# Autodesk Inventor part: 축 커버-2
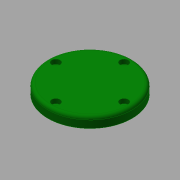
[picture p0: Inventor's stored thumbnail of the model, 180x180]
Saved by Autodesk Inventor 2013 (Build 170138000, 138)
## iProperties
Created: 2015-10
Part Number: 축 커버-2
Document SubType Name: Modeling
Designer: mdu
Density: 7.86 g/cm^3
Material: 강철, 연강
Mass: 403.237 g
Surface Area: 134.748 cm^2
Volume: 51.3024 cm^3
Author: mdu
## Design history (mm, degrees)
sketch "스케치1"
  geometry: C1 r 40 at (0, 0) reference; C2 r 26 at (0, 0) reference; 1 further point
  node "참조1"
  node "참조2"
extrude "돌출1" new body sketch "스케치1" distance "d0" = 10; taper "d1" = 0 deg
extrude "돌출2" join sketch "스케치1" distance "d2" = 3; taper "d3" = 0 deg
sketch "스케치2"
  geometry: C1 r 20 at (0, 0); 1 further point
  constraints: 1 centre point, 1 coincident
  dimensions: "d13" = 40 diameter of C1
extrude "돌출3" cut sketch "스케치2" distance "d14" = 3; taper "d15" = 0 deg
sketch "스케치3"
  geometry: C1 r 1.621 at (0, 32.5) reference; 1 further point
hole "구멍2" sketch "스케치3" at (0, 32.5) diameter "d16" = 4.5; stored, may be unused: countersink angle "d20" = 90 deg, drill point angle "d22" = 118 deg; dims "d17" = 6, "d18" = 8, "d19" = 4.4, "d21" = 8
fillet "모깎기1" dims "d26" = 3, "d27" = 0.3
chamfer "모따기1" distance "d28" = 1; stored, may be unused: second distance "d29" = 2, angle "d30" = 45 deg
node "솔리드1"
pattern_circular "원형 패턴1" dims angle "d24" = 360 deg
node "참조3"
